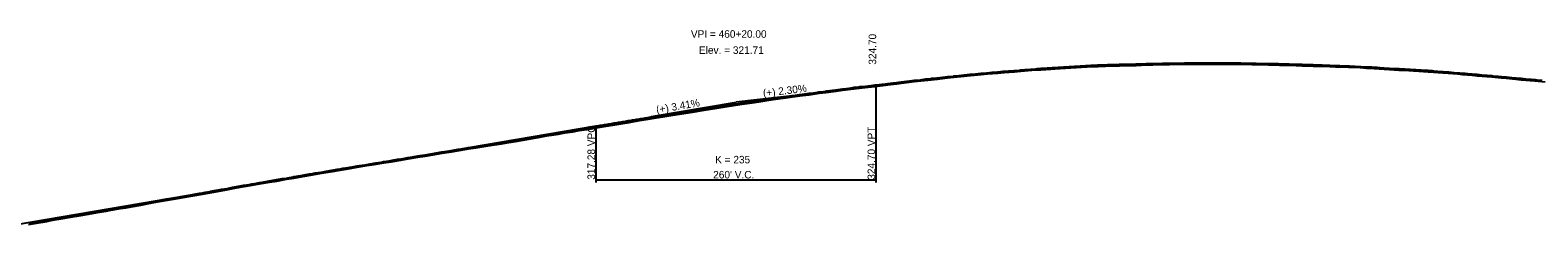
# Model space of a CAD drawing. Extents: x 1876258 to 1926563, y 729739 to 834437.
# Drawn here: x 1923728 to 1925127, y 828957 to 829138 of the extents above; entities that cross this region are included whole.
import ezdxf

# ---------------------------------------------------------------- set-up
doc = ezdxf.new("R2010")
doc.units = 0
for name, color, linetype in [('RD_EX_BldgApp', 7, 'Continuous'), ('RD_EX_H2O_BlueLn', 7, 'Continuous'), ('RD_EX_RailRoad', 7, 'Continuous'), ('RD_HC_Data', 7, 'Continuous'), ('RD_HC_Data_Tic', 7, 'Continuous'), ('RD_HC_TX_Sta50', 7, 'Continuous'), ('RD_PD_ALT5_CL', 7, 'Continuous')]:
    doc.layers.add(name, color=color, linetype=linetype)

msp = doc.modelspace()

# ---------------------------------------------------------------- linework, layer by layer
at = {"layer": 'RD_EX_BldgApp'}
for points in [[(1924118.9, 829025.2), (1924125.9, 829026.4), (1924134.7, 829027.8), (1924141.6, 829029), (1924150.6, 829030.3), (1924156.7, 829031.3), (1924165.2, 829032.7), (1924172, 829033.8), (1924178.3, 829034.9), (1924183.6, 829035.8), (1924192.1, 829037.3), (1924199.2, 829038.5), (1924207, 829039.9), (1924214, 829041), (1924218.1, 829041.7), (1924224.2, 829042.7), (1924231.4, 829043.9), (1924237.5, 829044.9), (1924246.9, 829046.4), (1924253.2, 829047.5), (1924262.4, 829049), (1924268.5, 829050.1), (1924277.9, 829051.5), (1924283.9, 829052.5), (1924293.4, 829054.2), (1924299.5, 829055.1), (1924308.9, 829056.7), (1924314.9, 829057.7), (1924324.4, 829059.2), (1924330.4, 829060.1), (1924338.7, 829061.5), (1924342.6, 829062.1), (1924353.5, 829063.8), (1924357.4, 829064.5), (1924366.9, 829066), (1924373, 829067), (1924382.5, 829068.5), (1924388.6, 829069.4), (1924398, 829070.9), (1924404.1, 829071.8), (1924413.5, 829073.2), (1924419.7, 829074.1), (1924429.2, 829075.4), (1924435.3, 829076.2), (1924444.6, 829077.5), (1924450.8, 829078.3), (1924460.2, 829079.6), (1924466.4, 829080.4), (1924475.8, 829081.7), (1924481.9, 829082.5), (1924491.7, 829083.8), (1924497.3, 829084.5), (1924505.8, 829085.4), (1924511.9, 829086.1), (1924521.8, 829087.3), (1924526.3, 829087.7), (1924532.2, 829088.4), (1924541.3, 829089.6), (1924548.5, 829090.5), (1924554.4, 829091.1), (1924564, 829092.3), (1924569.9, 829092.9), (1924579.4, 829093.9), (1924585.3, 829094.5), (1924594.8, 829095.5), (1924600.8, 829096.1), (1924610.5, 829097), (1924616.3, 829097.6), (1924626.1, 829098.5), (1924631.9, 829098.9), (1924641.6, 829099.7), (1924647.3, 829100.2), (1924657.5, 829101), (1924662.6, 829101.4), (1924666, 829101.6), (1924675.2, 829102.1), (1924679.1, 829102.4), (1924688.9, 829103), (1924693.9, 829103.4), (1924703.8, 829103.9), (1924709, 829104.3), (1924719.1, 829104.7), (1924726.1, 829105), (1924736.2, 829105.2), (1924738.9, 829105.3), (1924749, 829105.5), (1924754.4, 829105.6), (1924764.6, 829106), (1924769.8, 829106.1), (1924780.1, 829106.4), (1924785.3, 829106.5), (1924795.5, 829106.6), (1924800.8, 829106.7), (1924811.8, 829106.8), (1924817.1, 829106.8), (1924826.1, 829106.7), (1924831, 829106.7), (1924836.1, 829106.7), (1924846.2, 829106.7), (1924851.7, 829106.6), (1924861.8, 829106.3)], [(1924861.8, 829106.3), (1924871.7, 829106.3), (1924877.3, 829106.1), (1924887.5, 829105.9), (1924892.9, 829105.8), (1924903, 829105.5), (1924908.5, 829105.3), (1924918.6, 829105), (1924924.1, 829104.9), (1924934.1, 829104.5), (1924939.5, 829104.3), (1924943.5, 829104.1), (1924951.4, 829104), (1924955.7, 829103.8), (1924962.3, 829103.5), (1924968.2, 829103.1), (1924971, 829103), (1924975.4, 829102.7), (1924984.8, 829102.1), (1924989.7, 829101.8), (1924998.3, 829101.3), (1925003.2, 829101), (1925011.9, 829100.5), (1925016.8, 829100.2), (1925025.5, 829099.7), (1925030.4, 829099.4), (1925039, 829098.6), (1925044, 829098.3), (1925052.6, 829097.6), (1925057.5, 829097.2), (1925066.2, 829096.4), (1925071, 829096), (1925079.8, 829095.2), (1925084.6, 829094.8), (1925093.4, 829094), (1925098, 829093.6), (1925106.9, 829092.8), (1925111.7, 829092.3), (1925120.1, 829091.6), (1925124.6, 829091.1), (1925134.2, 829090.2)], [(1923726.3, 828957.5), (1923733.8, 828958.7), (1923743.2, 828960.5), (1923748.6, 828961.5), (1923758.1, 828963.1), (1923765.2, 828964.4), (1923774.8, 828965.9), (1923781.8, 828967.2), (1923792.2, 828968.9), (1923798.2, 828970), (1923802.6, 828970.8), (1923811.5, 828972.3), (1923816.5, 828973.2), (1923823.5, 828974.4), (1923830.4, 828975.6), (1923839.6, 828977.3), (1923846, 828978.5), (1923855.2, 828980.2), (1923862.6, 828981.4), (1923871.7, 828983.1), (1923878.7, 828984.3), (1923887.8, 828985.9), (1923894.8, 828987.1), (1923901.7, 828988.3), (1923908.4, 828989.5), (1923917.7, 828991.3), (1923924.5, 828992.5), (1923933.8, 828994.1), (1923940.7, 828995.3), (1923949.8, 828996.9), (1923956.7, 828998), (1923965.8, 828999.6), (1923972.6, 829000.8), (1923980.9, 829002.3), (1923990, 829003.8), (1923998.3, 829005.2), (1924008.4, 829007), (1924015.6, 829008.2), (1924024.7, 829009.7), (1924031.4, 829010.9), (1924040.4, 829012.3), (1924047.1, 829013.4), (1924056.2, 829014.9), (1924062.9, 829016), (1924072, 829017.5), (1924078.6, 829018.6), (1924087.7, 829020.1), (1924094.4, 829021.2), (1924103.3, 829022.8), (1924110.2, 829023.9), (1924118.9, 829025.2)]]:
    msp.add_lwpolyline(points, dxfattribs=at)
at = {"layer": 'RD_EX_H2O_BlueLn'}
for p, q in [((1924513.1, 828996.7), (1924513.1, 829086.3)), ((1924253.1, 828996.7), (1924253.1, 829049.2)), ((1924253.1, 828999.2), (1924513.1, 828999.2))]:
    msp.add_line(p, q, dxfattribs=at)
at = {"layer": 'RD_HC_Data_Tic'}
msp.add_lwpolyline([(1923726.8, 828958.8), (1923731.9, 828959.7), (1923733.5, 828960), (1923737, 828960.6), (1923742.1, 828961.6), (1923742.9, 828961.8), (1923747.2, 828962.5), (1923748.3, 828962.7), (1923752.3, 828963.4), (1923757.4, 828964.3), (1923757.9, 828964.4), (1923762.5, 828965.2), (1923765, 828965.6), (1923767.7, 828966), (1923772.8, 828966.9), (1923774.6, 828967.2), (1923777.9, 828967.8), (1923781.6, 828968.4), (1923783, 828968.6), (1923788.1, 828969.5), (1923792, 828970.1), (1923793.2, 828970.3), (1923798, 828971.3), (1923798.3, 828971.3), (1923802.4, 828972), (1923803.4, 828972.2), (1923808.5, 828973.1), (1923811.3, 828973.5), (1923813.6, 828973.9), (1923816.3, 828974.4), (1923818.7, 828974.8), (1923823.3, 828975.6), (1923823.8, 828975.7), (1923828.9, 828976.6), (1923830.1, 828976.8), (1923834, 828977.5), (1923839.1, 828978.5), (1923839.3, 828978.5), (1923844.2, 828979.4), (1923845.7, 828979.7), (1923849.3, 828980.4), (1923854.4, 828981.3), (1923855, 828981.4), (1923859.6, 828982.2), (1923862.4, 828982.6), (1923864.7, 828983), (1923869.8, 828984), (1923871.5, 828984.3), (1923874.9, 828984.9), (1923878.5, 828985.5), (1923880, 828985.8), (1923885.1, 828986.7), (1923887.6, 828987.1), (1923890.2, 828987.6), (1923894.6, 828988.3), (1923895.3, 828988.5), (1923900.4, 828989.4), (1923901.5, 828989.5), (1923905.5, 828990.3), (1923908.2, 828990.7), (1923910.6, 828991.2), (1923915.7, 828992.2), (1923917.5, 828992.5), (1923920.8, 828993.1), (1923924.3, 828993.7), (1923925.9, 828994), (1923931.1, 828994.9), (1923933.6, 828995.4), (1923936.2, 828995.8), (1923940.5, 828996.6), (1923941.3, 828996.7), (1923946.4, 828997.6), (1923949.6, 828998.1), (1923951.5, 828998.4), (1923956.5, 828999.3), (1923956.6, 828999.3), (1923961.7, 829000.2), (1923965.6, 829000.8), (1923966.8, 829001.1), (1923971.9, 829002), (1923972.4, 829002.1), (1923977, 829002.9), (1923980.7, 829003.5), (1923982.1, 829003.7), (1923987.2, 829004.6), (1923989.7, 829005.1), (1923992.3, 829005.5), (1923997.5, 829006.3), (1923998.1, 829006.4), (1924002.6, 829007.2), (1924007.7, 829008.1), (1924008.2, 829008.2), (1924012.8, 829009), (1924015.4, 829009.5), (1924017.9, 829009.9), (1924023, 829010.7), (1924024.4, 829010.9), (1924028.1, 829011.6), (1924031.2, 829012.1), (1924033.2, 829012.4), (1924038.3, 829013.2), (1924040.2, 829013.5), (1924043.4, 829014), (1924046.9, 829014.6), (1924048.5, 829014.9), (1924053.6, 829015.7), (1924055.9, 829016.1), (1924058.7, 829016.6), (1924062.7, 829017.2), (1924063.8, 829017.4), (1924068.9, 829018.2), (1924071.8, 829018.7), (1924074, 829019.1), (1924078.4, 829019.8), (1924079.2, 829020), (1924084.3, 829020.8), (1924087.5, 829021.3), (1924089.4, 829021.6), (1924094.2, 829022.4), (1924094.5, 829022.5), (1924099.6, 829023.4), (1924103.1, 829024), (1924104.7, 829024.3), (1924109.8, 829025.1), (1924110, 829025.1), (1924114.9, 829025.9), (1924118.7, 829026.5), (1924120, 829026.7), (1924125.1, 829027.5), (1924125.7, 829027.6), (1924130.2, 829028.4), (1924134.5, 829029.1), (1924135.3, 829029.2), (1924140.4, 829030.1), (1924141.4, 829030.2), (1924145.6, 829030.8), (1924150.4, 829031.5), (1924150.7, 829031.6), (1924155.8, 829032.4), (1924156.5, 829032.5), (1924160.9, 829033.3), (1924165, 829033.9), (1924166, 829034.1), (1924171.1, 829035), (1924171.8, 829035.1), (1924176.2, 829035.8), (1924178.1, 829036.1), (1924181.3, 829036.7), (1924183.4, 829037), (1924186.4, 829037.6), (1924191.5, 829038.5), (1924191.9, 829038.6), (1924196.6, 829039.3), (1924199, 829039.7), (1924201.7, 829040.2), (1924206.8, 829041.1), (1924206.8, 829041.1), (1924211.9, 829041.9), (1924213.8, 829042.2), (1924217, 829042.8), (1924217.9, 829043), (1924222.1, 829043.7), (1924224, 829044), (1924227.3, 829044.5), (1924231.2, 829045.1), (1924232.4, 829045.3), (1924237.3, 829046.1), (1924237.5, 829046.1), (1924242.6, 829047), (1924246.7, 829047.6), (1924247.7, 829047.8), (1924252.8, 829048.7), (1924252.9, 829048.8), (1924257.9, 829049.6), (1924262.2, 829050.3), (1924263, 829050.4), (1924268.1, 829051.3), (1924268.3, 829051.3), (1924273.2, 829052), (1924277.7, 829052.7), (1924278.3, 829052.8), (1924283.4, 829053.7), (1924283.7, 829053.7), (1924288.5, 829054.6), (1924293.2, 829055.4), (1924293.6, 829055.5), (1924298.7, 829056.3), (1924299.3, 829056.4), (1924303.9, 829057.1), (1924308.7, 829057.9), (1924309, 829058), (1924314.1, 829058.8), (1924314.7, 829058.9), (1924319.2, 829059.6), (1924324.2, 829060.4), (1924324.3, 829060.4), (1924329.4, 829061.3), (1924330.2, 829061.4), (1924334.5, 829062.1), (1924338.5, 829062.7), (1924339.6, 829062.9), (1924342.4, 829063.3), (1924344.7, 829063.7), (1924349.8, 829064.5), (1924353.3, 829065.1), (1924354.9, 829065.3), (1924357.2, 829065.7), (1924360, 829066.2), (1924365.1, 829067), (1924366.7, 829067.3), (1924370.2, 829067.8), (1924372.8, 829068.2), (1924375.4, 829068.6), (1924380.5, 829069.4), (1924382.4, 829069.7), (1924385.6, 829070.2), (1924388.4, 829070.6), (1924390.7, 829071), (1924395.8, 829071.8), (1924397.9, 829072.1), (1924400.9, 829072.6), (1924403.9, 829073), (1924406, 829073.3), (1924411.1, 829074.1), (1924413.3, 829074.4), (1924416.2, 829074.8), (1924419.5, 829075.3), (1924421.3, 829075.6), (1924426.4, 829076.3), (1924429, 829076.6), (1924431.5, 829077), (1924435.1, 829077.5), (1924436.7, 829077.7), (1924441.8, 829078.4), (1924444.4, 829078.7), (1924446.9, 829079.1), (1924450.6, 829079.6), (1924452, 829079.8), (1924457.1, 829080.5), (1924460, 829080.9), (1924462.2, 829081.1), (1924466.2, 829081.7), (1924467.3, 829081.8), (1924472.4, 829082.5), (1924475.6, 829083), (1924477.5, 829083.2), (1924481.8, 829083.7), (1924482.6, 829083.9), (1924487.7, 829084.5), (1924491.5, 829085), (1924492.8, 829085.2), (1924497.1, 829085.7), (1924498, 829085.8), (1924503.1, 829086.4), (1924505.7, 829086.7), (1924508.2, 829087), (1924511.7, 829087.4), (1924513.3, 829087.6), (1924518.4, 829088.2), (1924521.7, 829088.5), (1924523.5, 829088.7), (1924526.1, 829089), (1924528.6, 829089.3), (1924532, 829089.7), (1924533.7, 829089.9), (1924538.8, 829090.5), (1924541.2, 829090.8), (1924543.9, 829091.1), (1924548.4, 829091.7), (1924549, 829091.8), (1924554.1, 829092.3), (1924554.3, 829092.3), (1924559.2, 829093), (1924563.9, 829093.5), (1924564.4, 829093.6), (1924569.5, 829094.1), (1924569.8, 829094.1), (1924574.6, 829094.6), (1924579.3, 829095.1), (1924579.7, 829095.1), (1924584.8, 829095.7), (1924585.2, 829095.8), (1924589.9, 829096.3), (1924594.7, 829096.7), (1924595, 829096.8), (1924600.1, 829097.3), (1924600.7, 829097.3), (1924605.2, 829097.8), (1924610.3, 829098.3), (1924610.4, 829098.3), (1924615.4, 829098.8), (1924616.2, 829098.8), (1924620.5, 829099.2), (1924625.7, 829099.7), (1924626, 829099.7), (1924630.8, 829100.1), (1924631.8, 829100.2), (1924635.9, 829100.5), (1924641, 829100.9), (1924641.5, 829100.9), (1924646.1, 829101.3), (1924647.2, 829101.4), (1924651.2, 829101.7), (1924656.3, 829102.1), (1924657.4, 829102.2), (1924661.4, 829102.5), (1924662.5, 829102.6), (1924665.9, 829102.9), (1924666.6, 829102.9), (1924671.7, 829103.2), (1924675.1, 829103.4), (1924676.8, 829103.5), (1924679, 829103.6), (1924681.9, 829103.8), (1924687, 829104.2), (1924688.8, 829104.3), (1924692.1, 829104.5), (1924693.9, 829104.6), (1924697.2, 829104.8), (1924702.3, 829105.1), (1924703.7, 829105.2), (1924707.4, 829105.4), (1924709, 829105.5), (1924712.5, 829105.7), (1924717.6, 829105.9), (1924719, 829106), (1924722.7, 829106.1), (1924726.1, 829106.2), (1924727.9, 829106.3), (1924733, 829106.4), (1924736.1, 829106.4), (1924738.1, 829106.5), (1924738.9, 829106.6), (1924743.2, 829106.6), (1924748.3, 829106.7), (1924749, 829106.7), (1924753.4, 829106.8), (1924754.3, 829106.9), (1924758.5, 829107), (1924763.6, 829107.2), (1924764.5, 829107.2), (1924768.7, 829107.3), (1924769.8, 829107.4), (1924773.8, 829107.5), (1924778.9, 829107.6), (1924780, 829107.6), (1924784, 829107.7), (1924785.3, 829107.7), (1924789.2, 829107.8), (1924794.3, 829107.8), (1924795.5, 829107.8), (1924799.4, 829107.9), (1924800.7, 829108), (1924804.5, 829108), (1924809.6, 829108), (1924811.8, 829108), (1924814.7, 829108.1), (1924817.1, 829108.1), (1924819.8, 829108), (1924824.9, 829108), (1924826.1, 829108), (1924830, 829108), (1924831, 829108), (1924835.1, 829108), (1924836.1, 829108), (1924840.3, 829108), (1924845.4, 829107.9), (1924846.2, 829107.9), (1924850.5, 829107.9), (1924851.7, 829107.9), (1924855.6, 829107.8), (1924860.7, 829107.6), (1924861.8, 829107.6), (1924865.8, 829107.6), (1924870.9, 829107.5), (1924871.8, 829107.5), (1924876, 829107.4), (1924877.4, 829107.4), (1924881.1, 829107.3), (1924886.2, 829107.2), (1924887.5, 829107.1), (1924891.3, 829107.1), (1924892.9, 829107), (1924896.5, 829106.9), (1924901.6, 829106.8), (1924903.1, 829106.7), (1924906.7, 829106.6), (1924908.5, 829106.6), (1924911.8, 829106.5), (1924916.9, 829106.3), (1924918.6, 829106.3), (1924922, 829106.2), (1924924.1, 829106.1), (1924927.1, 829106), (1924932.2, 829105.8), (1924934.1, 829105.7), (1924937.3, 829105.6), (1924939.5, 829105.5), (1924942.4, 829105.4), (1924943.5, 829105.4), (1924947.5, 829105.3), (1924951.5, 829105.2), (1924952.6, 829105.2), (1924955.7, 829105), (1924957.8, 829104.9), (1924962.4, 829104.7), (1924962.9, 829104.7), (1924968, 829104.4), (1924968.2, 829104.4), (1924971, 829104.2), (1924973.1, 829104.1), (1924975.5, 829104), (1924978.2, 829103.8), (1924983.3, 829103.4), (1924984.8, 829103.3), (1924988.4, 829103.1), (1924989.7, 829103.1), (1924993.5, 829102.8), (1924998.4, 829102.6), (1924998.6, 829102.6), (1925003.3, 829102.3), (1925003.7, 829102.3), (1925008.8, 829102), (1925012, 829101.8), (1925013.9, 829101.7), (1925016.8, 829101.5), (1925019.1, 829101.4), (1925024.2, 829101.1), (1925025.6, 829101), (1925029.3, 829100.7), (1925030.5, 829100.6), (1925034.4, 829100.3), (1925039.1, 829099.9), (1925039.5, 829099.9), (1925044.1, 829099.5), (1925044.6, 829099.5), (1925049.7, 829099.1), (1925052.7, 829098.8), (1925054.8, 829098.7), (1925057.6, 829098.5), (1925059.9, 829098.3), (1925065.1, 829097.8), (1925066.3, 829097.6), (1925070.1, 829097.3), (1925071.1, 829097.3), (1925075.3, 829096.9), (1925079.9, 829096.5), (1925080.4, 829096.4), (1925084.7, 829096.1), (1925085.5, 829096), (1925090.6, 829095.5), (1925093.5, 829095.2), (1925095.7, 829095), (1925098.2, 829094.8), (1925100.8, 829094.6), (1925105.9, 829094.1), (1925107.1, 829094), (1925111, 829093.7), (1925111.8, 829093.6), (1925116.1, 829093.2), (1925120.2, 829092.8), (1925121.2, 829092.7), (1925124.7, 829092.4), (1925126.3, 829092.2), (1925131.4, 829091.7)], dxfattribs=at)
at = {"layer": 'RD_HC_TX_Sta50'}
for p in [(1924462.6, 829080.5), (1924304.2, 829057.9)]:
    msp.add_line(p, (1924383.1, 829071.3), dxfattribs=at)
at = {"layer": 'RD_PD_ALT5_CL'}
msp.add_line((1923713.1, 828957.2), (1924253.1, 829049.2), dxfattribs=at)
msp.add_spline([(1924253.1, 829049.2), (1924258.3, 829050.1), (1924263.5, 829050.9), (1924268.7, 829051.8), (1924273.9, 829052.7), (1924279.1, 829053.5), (1924284.3, 829054.4), (1924289.5, 829055.2), (1924294.7, 829056.1), (1924299.9, 829056.9), (1924305.1, 829057.8), (1924310.3, 829058.6), (1924315.5, 829059.4), (1924320.7, 829060.2), (1924325.9, 829061), (1924331.1, 829061.8), (1924336.3, 829062.6), (1924341.5, 829063.4), (1924346.7, 829064.2), (1924351.9, 829065), (1924357.1, 829065.8), (1924362.3, 829066.5), (1924367.5, 829067.3), (1924372.7, 829068), (1924377.9, 829068.8), (1924383.1, 829069.5), (1924388.3, 829070.3), (1924393.5, 829071), (1924398.7, 829071.7), (1924403.9, 829072.5), (1924409.1, 829073.2), (1924414.3, 829073.9), (1924419.5, 829074.6), (1924424.7, 829075.3), (1924429.9, 829076), (1924435.1, 829076.7), (1924440.3, 829077.3), (1924445.5, 829078), (1924450.7, 829078.7), (1924455.9, 829079.4), (1924461.1, 829080), (1924466.3, 829080.7), (1924471.5, 829081.3), (1924476.7, 829082), (1924481.9, 829082.6), (1924487.1, 829083.2), (1924492.3, 829083.8), (1924497.5, 829084.5), (1924502.7, 829085.1), (1924507.9, 829085.7), (1924513.1, 829086.3)], degree=3, dxfattribs=at)

# ---------------------------------------------------------------- texts
at = {"layer": 'RD_EX_H2O_BlueLn'}
for s, p in [('K = 235', (1924363.6, 829014.4)), ("260' V.C.", (1924361.8, 829000.4))]:
    msp.add_text(s, height=7, dxfattribs=at).set_placement(p)
at = {"layer": 'RD_EX_RailRoad'}
for s, p in [('317.28 VPC', (1924252.1, 828999.2)), ('324.70 VPT', (1924512.1, 828999.2))]:
    msp.add_text(s, height=7, rotation=90, dxfattribs=at).set_placement(p)
at = {"layer": 'RD_HC_Data'}
for s, p in [('VPI = 460+20.00', (1924341.1, 829131.3)), ('Elev. = 321.71', (1924348.6, 829116.3))]:
    msp.add_text(s, height=7, dxfattribs=at).set_placement(p)
msp.add_text('324.70', height=7, rotation=90, dxfattribs=at).set_placement((1924513.1, 829106.3))
at = {"layer": 'RD_HC_TX_Sta50'}
for s, rotation, p in [('(+) 2.30%', 6.5602, (1924408.4, 829076.3)), ('(+) 3.41%', 9.6699, (1924309.5, 829060.8))]:
    msp.add_text(s, height=7, rotation=rotation, dxfattribs=at).set_placement(p)

doc.saveas('drawing.dxf')
